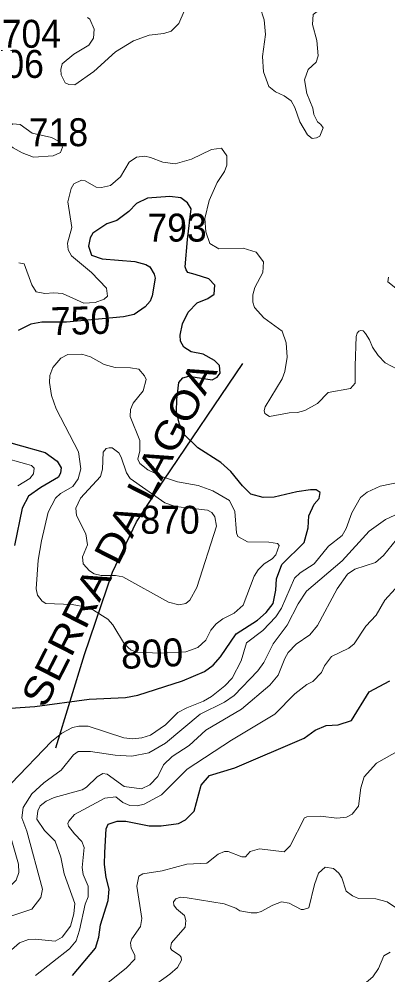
# Model space of a CAD drawing. Extents: x 499.9 to 555.3, y 9281.5 to 9336.8.
# Drawn here: x 540.62 to 542.72, y 9284.25 to 9289.72 of the extents above; entities that cross this region are included whole.
import ezdxf
from ezdxf.enums import TextEntityAlignment as Align

# ---------------------------------------------------------------- set-up
doc = ezdxf.new("R2010")
doc.units = 0
doc.header["$LTSCALE"] = 0.064
for name, color, linetype, lineweight in [('1', 7, 'Continuous', 25), ('2', 7, 'Continuous', 13), ('26', 7, 'Continuous', 25)]:
    doc.layers.add(name, color=color, linetype=linetype, lineweight=lineweight)
doc.layers.add('21', color=7, linetype='Continuous')
doc.layers.add('61', color=7, linetype='Continuous')

msp = doc.modelspace()

# ---------------------------------------------------------------- linework, layer by layer
at = {"layer": '1'}
for points in [[(541.6227, 9288.262), (541.5806, 9288.2744), (541.5701, 9288.289), (541.5654, 9288.3054), (541.578, 9288.4627), (541.5992, 9288.638), (541.5787, 9288.6731), (541.5405, 9288.7), (541.4766, 9288.7081), (541.3506, 9288.6982), (541.2871, 9288.6677), (541.243, 9288.6223), (541.1753, 9288.5719), (541.1182, 9288.5517), (541.0363, 9288.498), (541.0226, 9288.4717), (541.0126, 9288.4249), (541.0293, 9288.3723), (541.0913, 9288.3512), (541.2781, 9288.3373), (541.3409, 9288.3184), (541.3638, 9288.3053), (541.3875, 9288.2649), (541.394, 9288.2419), (541.3769, 9288.1409), (541.366, 9288.1101), (541.3368, 9288.0765), (541.274, 9288.0324), (541.212, 9288.0192), (541.0095, 9288), (540.8874, 9287.9885), (540.7455, 9287.99), (540.6821, 9287.9773), (540.6097, 9287.9425)], [(541.7302, 9288.1499), (541.7343, 9288.2004), (541.7014, 9288.2371), (541.6227, 9288.262)], [(540.5659, 9285.7798), (540.7065, 9285.7902), (541.0157, 9285.8315), (541.2248, 9285.8404), (541.295, 9285.8542), (541.5506, 9285.9365), (541.6759, 9285.9899), (541.7262, 9286.026), (541.7677, 9286.0735), (541.8575, 9286.206), (541.9797, 9286.2834), (542.0293, 9286.3273), (542.0676, 9286.379), (542.0834, 9286.4562), (542.0884, 9286.5198), (542.1178, 9286.6028), (542.2455, 9286.7285), (542.2679, 9286.8127), (542.2717, 9286.8803), (542.302, 9286.947), (542.3311, 9286.9792), (542.3375, 9287.0139), (542.3139, 9287.0289), (542.2817, 9287.0288), (542.2035, 9287.0177), (542.0738, 9286.9878), (542.0113, 9286.9862), (541.941, 9287.0051), (541.8935, 9287.0521), (541.8255, 9287.1342), (541.7698, 9287.1866), (541.6371, 9287.2701), (541.5552, 9287.3508), (541.5312, 9287.4111), (541.5153, 9287.4788), (541.517, 9287.5469), (541.5298, 9287.6448), (541.5524, 9287.6711), (541.5869, 9287.6797), (541.7204, 9287.6598), (541.748, 9287.6737), (541.7649, 9287.6979), (541.7616, 9287.7404), (541.7331, 9287.7707), (541.6688, 9287.8059), (541.5999, 9287.8204), (541.5569, 9287.8459), (541.5392, 9287.8798), (541.5361, 9287.914), (541.5501, 9287.9801), (541.5833, 9288.0469), (541.6331, 9288.1), (541.6942, 9288.1254), (541.7302, 9288.1499)], [(540.4919, 9287.3189), (540.7655, 9287.2438), (540.8332, 9287.1935), (540.856, 9287.1548), (540.853, 9287.1279), (540.8412, 9287.102), (540.7394, 9287.0429), (540.6691, 9286.9937), (540.633, 9286.9252), (540.5889, 9286.7108)], [(540.9216, 9284.2502), (541.0523, 9284.4071), (541.0711, 9284.47), (541.081, 9284.5407), (541.1254, 9284.6789), (541.1314, 9284.7436), (541.1126, 9284.8105), (541.1047, 9284.8849), (541.1065, 9284.9548), (541.1141, 9285.09), (541.1257, 9285.1157), (541.1765, 9285.1335), (541.2251, 9285.1328), (541.3585, 9285.1066), (541.4277, 9285.1066), (541.5264, 9285.1201), (541.5667, 9285.1406), (541.6169, 9285.191), (541.6571, 9285.3388), (541.7047, 9285.3943), (541.8486, 9285.4395), (542.2465, 9285.6092), (542.3088, 9285.6551), (542.3712, 9285.6818), (542.4407, 9285.6845), (542.517, 9285.7097), (542.6178, 9285.873), (542.7356, 9285.936)]]:
    msp.add_lwpolyline(points, dxfattribs=at)
at = {"layer": '2'}
for points in [[(541.9666, 9289.8735), (542.0165, 9289.7189), (542.0245, 9289.6354), (542.0072, 9289.5096), (542.0127, 9289.4227), (542.0434, 9289.3377), (542.0819, 9289.3068), (542.1318, 9289.2838), (542.1707, 9289.2556), (542.1919, 9289.2184), (542.2207, 9289.1357), (542.2645, 9289.0607), (542.2922, 9289.0413), (542.3157, 9289.0443), (542.3355, 9289.0537), (542.3549, 9289.1019), (542.3416, 9289.1213), (542.321, 9289.1359)], [(542.2679, 9289.4348), (542.3151, 9289.4781), (542.3253, 9289.5128), (542.3189, 9289.6011), (542.2931, 9289.6931), (542.2968, 9289.7499), (542.3944, 9289.8232), (542.4483, 9289.902), (542.4756, 9289.9209), (542.5321, 9289.9128), (542.5753, 9289.8797), (542.6539, 9289.843), (542.8073, 9289.8288)], [(541.0067, 9289.7334), (541.0197, 9289.7224), (541.0454, 9289.6663), (541.042, 9289.6149), (541.0136, 9289.5742), (540.928, 9289.5231), (540.8627, 9289.4682), (540.8537, 9289.4351), (540.8564, 9289.4044), (540.8793, 9289.3596), (540.9009, 9289.3498), (540.9334, 9289.3466), (541.0431, 9289.424), (541.1668, 9289.5363), (541.2704, 9289.6), (541.3601, 9289.6311), (541.4436, 9289.641), (541.4855, 9289.6543), (541.5282, 9289.6989), (541.5965, 9289.8557)], [(542.321, 9289.1359), (542.3014, 9289.1786), (542.2947, 9289.2134), (542.2612, 9289.2973), (542.2476, 9289.3765), (542.2679, 9289.4348)], [(541.8967, 9288.4132), (541.7585, 9288.4093), (541.7069, 9288.4391), (541.6826, 9288.5065), (541.6779, 9288.5823), (541.7017, 9288.685), (541.7484, 9288.7879), (541.7904, 9288.8515), (541.8031, 9288.8882), (541.8032, 9288.9415), (541.7725, 9288.9846), (541.7163, 9288.9772), (541.602, 9288.9213), (541.5072, 9288.8946), (541.438, 9288.9054), (541.3679, 9288.9323), (541.3352, 9288.9385), (541.2872, 9288.9344), (541.2448, 9288.9054), (541.1957, 9288.8219), (541.138, 9288.772), (541.0871, 9288.7593), (541.0569, 9288.7622), (540.9938, 9288.7985), (540.9719, 9288.8017), (540.9287, 9288.78), (540.9134, 9288.7536), (540.8947, 9288.6783), (540.9168, 9288.5314), (540.8933, 9288.4409), (540.8965, 9288.4038), (540.9157, 9288.369), (541.0287, 9288.2732), (541.1151, 9288.1836), (541.1202, 9288.1377), (541.1021, 9288.1213), (541.0498, 9288.1024), (540.9861, 9288.0979), (540.8634, 9288.1527), (540.8141, 9288.1574), (540.7624, 9288.1529), (540.7135, 9288.1636), (540.6877, 9288.2038), (540.6447, 9288.3222), (540.6136, 9288.3292)], [(542.7816, 9287.7189), (542.7095, 9287.7561), (542.6679, 9287.7979), (542.6361, 9287.8466), (542.6196, 9287.8885), (542.5967, 9287.9252), (542.5823, 9287.9393), (542.5692, 9287.9419), (542.5587, 9287.9378), (542.5496, 9287.927), (542.5436, 9287.9067), (542.537, 9287.7398), (542.5379, 9287.6397), (542.5098, 9287.6099), (542.3828, 9287.5875), (542.3214, 9287.5238), (542.2496, 9287.483), (542.2083, 9287.4719), (542.1603, 9287.4708), (542.0481, 9287.4496), (542.0208, 9287.4662), (542.0168, 9287.4836), (542.0235, 9287.5041), (542.1206, 9287.6641), (542.1359, 9287.7071), (542.1485, 9287.7892), (542.1423, 9287.8719), (542.1205, 9287.9374), (542.016, 9288.0149), (541.9623, 9288.0724), (541.9531, 9288.1043), (541.9515, 9288.1464), (541.9645, 9288.1885), (542.0099, 9288.2738), (542.0132, 9288.3351), (541.9719, 9288.3897), (541.8967, 9288.4132)], [(542.7279, 9288.2475), (542.7237, 9288.2198), (542.7891, 9288.169)], [(540.5094, 9287.2181), (540.6598, 9287.1773), (540.687, 9287.1691), (540.7014, 9287.1543), (540.6985, 9287.1216), (540.6773, 9287.094), (540.6087, 9287.0518)], [(541.2136, 9285.6112), (541.2645, 9285.6048), (541.3182, 9285.61), (541.3672, 9285.6254), (541.4531, 9285.6843), (541.524, 9285.7547), (541.5743, 9285.7821), (541.6696, 9285.8196), (541.7157, 9285.8462), (541.7922, 9285.9076), (541.8339, 9285.9523), (541.8857, 9286.0512), (541.9166, 9286.1536), (542.0102, 9286.2239), (542.0839, 9286.3024), (542.1155, 9286.3519), (542.1913, 9286.5243), (542.2219, 9286.5547), (542.303, 9286.6058), (542.3846, 9286.7077), (542.4636, 9286.7683), (542.4866, 9286.8093), (542.5179, 9286.8987), (542.5679, 9286.9851), (542.6061, 9287.0167), (542.6803, 9287.0498), (542.9294, 9287.1022)], [(542.7649, 9286.8855), (542.7106, 9286.8604), (542.6167, 9286.7935), (542.4631, 9286.6243), (542.2589, 9286.4499), (542.2108, 9286.3766), (542.1486, 9286.2557), (542.0675, 9286.1489), (542.016, 9286.0417), (541.9802, 9285.9932), (541.8462, 9285.853), (541.7896, 9285.8152), (541.6506, 9285.7463), (541.4528, 9285.5798), (541.3568, 9285.525), (541.2603, 9285.5061), (541.1659, 9285.5108), (541.0234, 9285.533), (540.9535, 9285.5327), (540.9276, 9285.5133), (540.8556, 9285.4259), (540.7562, 9285.352), (540.6888, 9285.2906), (540.6384, 9285.2114), (540.6304, 9285.1518), (540.6591, 9285.0772), (540.7493, 9284.7444), (540.7402, 9284.6968), (540.689, 9284.6308), (540.5684, 9284.5905)], [(542.7731, 9286.7447), (542.6988, 9286.653), (542.6528, 9286.6131), (542.5361, 9286.5758), (542.4929, 9286.547)], [(542.4929, 9286.547), (542.4336, 9286.4641), (542.3211, 9286.2526), (542.2775, 9286.2), (542.2006, 9286.1467), (542.1545, 9286.0992)], [(540.7097, 9284.2512), (540.9045, 9284.402), (540.9418, 9284.4483), (540.9615, 9284.509), (540.9938, 9284.6581), (541.0109, 9284.6999), (541.0104, 9284.7625), (540.9824, 9284.8289), (540.9757, 9284.8678), (540.9881, 9284.9831), (540.9751, 9285.0163), (540.9316, 9285.0618), (540.8976, 9285.1051), (540.895, 9285.1202), (540.8999, 9285.1341), (540.9329, 9285.1716), (541.1063, 9285.2661), (541.1696, 9285.2734), (541.2097, 9285.2404), (541.2494, 9285.2225), (541.2901, 9285.2212), (541.3307, 9285.2314), (541.4298, 9285.2834), (541.5773, 9285.4307), (541.8297, 9285.5979), (542.0772, 9285.7454), (542.1927, 9285.862), (542.2618, 9285.9156), (542.2948, 9285.9337), (542.3439, 9285.9845), (542.3624, 9286.0223), (542.4014, 9286.0753), (542.502, 9286.1241), (542.5321, 9286.1475), (542.5987, 9286.2501), (542.6574, 9286.3124), (542.7069, 9286.3983), (542.7664, 9286.4628)], [(542.1545, 9286.0992), (542.1344, 9286.0646), (542.0964, 9285.9698), (542.0494, 9285.9113), (541.8876, 9285.775), (541.6827, 9285.6548), (541.5879, 9285.5674), (541.4914, 9285.5028), (541.4417, 9285.456), (541.408, 9285.3893), (541.363, 9285.341), (541.3154, 9285.3179), (541.2157, 9285.3314), (541.1196, 9285.4021), (541.0945, 9285.4054), (541.0623, 9285.387), (541.0017, 9285.3278), (540.9771, 9285.3126), (540.8167, 9285.2699), (540.7698, 9285.2484), (540.7359, 9285.2215), (540.7226, 9285.1932), (540.7167, 9285.1441), (540.7614, 9285.0807), (540.8227, 9285.0189), (540.8549, 9284.9276), (540.8739, 9284.8328), (540.9341, 9284.663), (540.9282, 9284.6025), (540.9086, 9284.532), (540.8626, 9284.4701), (540.8221, 9284.4462), (540.7066, 9284.4586), (540.6702, 9284.4555), (540.617, 9284.4375), (540.5713, 9284.3975)], [(540.8007, 9285.5887), (540.8596, 9285.6374), (540.9201, 9285.6698), (540.9575, 9285.6779), (541.0115, 9285.6776), (541.2136, 9285.6112)], [(539.4244, 9284.1395), (539.5556, 9284.2752), (539.7038, 9284.3291), (539.7533, 9284.3554), (539.7973, 9284.3883), (539.8761, 9284.4716), (539.9056, 9284.4948), (540.0845, 9284.5504), (540.1934, 9284.596), (540.2865, 9284.6502), (540.41, 9284.7447), (540.4473, 9284.7599), (540.5528, 9284.7508), (540.5991, 9284.7967), (540.6142, 9284.8396), (540.6126, 9284.8877), (540.5339, 9285.1604), (540.5254, 9285.229), (540.5413, 9285.2975), (540.5712, 9285.3499), (540.8007, 9285.5887)], [(541.104, 9284.194), (541.2303, 9284.2933), (541.277, 9284.343), (541.2778, 9284.3664), (541.2571, 9284.4071), (541.2529, 9284.4381), (541.2595, 9284.4608), (541.3097, 9284.5305), (541.3175, 9284.5763), (541.2879, 9284.7609), (541.3011, 9284.8197), (541.3241, 9284.8314), (541.4339, 9284.8496), (541.5741, 9284.8869), (541.6887, 9284.8935), (541.754, 9284.944), (541.7905, 9284.9599), (541.8103, 9284.9597), (541.8891, 9284.9298), (541.9097, 9284.9303), (541.9372, 9284.9599), (541.9912, 9284.9758), (542.131, 9284.9574), (542.1664, 9284.992), (542.2476, 9285.1522), (542.2617, 9285.159), (542.3388, 9285.1621), (542.4321, 9285.1513), (542.4879, 9285.1573), (542.5196, 9285.1741), (542.556, 9285.2187), (542.5691, 9285.3238), (542.5881, 9285.3874), (542.6591, 9285.4657), (542.79, 9285.5395)], [(542.7686, 9284.6401), (542.7198, 9284.6712), (542.6563, 9284.6894), (542.5564, 9284.6913), (542.5227, 9284.706), (542.4851, 9284.7338), (542.4608, 9284.8098), (542.4435, 9284.8369), (542.4134, 9284.8618), (542.3658, 9284.8703), (542.328, 9284.8361), (542.3051, 9284.7707), (542.2717, 9284.6384), (542.2426, 9284.6276), (542.2283, 9284.6288), (542.1597, 9284.6639), (542.1158, 9284.672), (542.0667, 9284.6534), (542.0007, 9284.6159), (541.9745, 9284.6084), (541.9426, 9284.6084), (541.8784, 9284.6209), (541.8542, 9284.6361), (541.7873, 9284.6608), (541.5773, 9284.6943), (541.5393, 9284.6984), (541.5112, 9284.6895), (541.4982, 9284.6716), (541.5007, 9284.6528), (541.5158, 9284.6318), (541.561, 9284.5938), (541.569, 9284.5644), (541.5645, 9284.5269), (541.4877, 9284.4367), (541.4818, 9284.4074), (541.489, 9284.3954), (541.533, 9284.3675), (541.5416, 9284.3558), (541.5436, 9284.3379), (541.5205, 9284.2956), (541.4777, 9284.2589), (541.3607, 9284.1746)], [(541.458, 9283.7571), (541.5417, 9283.8675), (541.6027, 9283.9145), (541.6733, 9283.9915), (541.7401, 9284.0831), (541.7695, 9284.1349), (541.7938, 9284.1738), (541.8084, 9284.1872), (541.8241, 9284.1854), (541.835, 9284.1745), (541.8494, 9284.1253), (541.883, 9283.8716), (541.9024, 9283.8267), (541.9617, 9283.7909), (541.9848, 9283.7904), (542.0602, 9283.829), (542.2188, 9283.9504), (542.3046, 9284.0061), (542.4392, 9284.0749), (542.6382, 9284.2418), (542.6705, 9284.2901), (542.7009, 9284.3625), (542.7382, 9284.3841)]]:
    msp.add_lwpolyline(points, dxfattribs=at)
for points in [[(540.5819, 9288.9879), (540.6341, 9288.9578), (540.6976, 9288.9336), (540.8099, 9288.9412), (540.8517, 9288.9609), (540.8635, 9288.9899), (540.8488, 9289.0205), (540.8016, 9289.0459), (540.6905, 9289.0718), (540.6213, 9289.1199), (540.5797, 9289.1249), (540.554, 9289.106), (540.5389, 9289.0851), (540.53, 9289.0452), (540.5556, 9289.0079)], [(541.2187, 9286.1465), (541.2563, 9286.1115), (541.2882, 9286.1008), (541.4227, 9286.0955), (541.5691, 9286.1035), (541.6369, 9286.1275), (541.6839, 9286.1688), (541.7116, 9286.2267), (541.7419, 9286.2624), (541.7809, 9286.2914), (541.846, 9286.3235), (541.896, 9286.3689), (541.9597, 9286.5363), (541.9827, 9286.5717), (542.0171, 9286.6063), (542.062, 9286.6341), (542.0829, 9286.6578), (542.1021, 9286.7107), (542.0927, 9286.7232), (542.0439, 9286.7297), (541.9211, 9286.7317), (541.8658, 9286.7618), (541.859, 9286.7841), (541.8497, 9286.9064), (541.8185, 9286.9689), (541.723, 9287.0246), (541.6394, 9287.054), (541.5208, 9287.0751), (541.4356, 9287.1046), (541.3514, 9287.1438), (541.3065, 9287.181), (541.2955, 9287.2047), (541.3051, 9287.2527), (541.3064, 9287.313), (541.2512, 9287.4501), (541.2527, 9287.4899), (541.2687, 9287.5259), (541.3252, 9287.5968), (541.3415, 9287.6609), (541.3336, 9287.6817), (541.3, 9287.7201), (541.2526, 9287.7278), (541.1641, 9287.7303), (541.1015, 9287.7464), (541.0234, 9287.7914), (540.9744, 9287.8053), (540.8937, 9287.8042), (540.854, 9287.783), (540.8083, 9287.7298), (540.7912, 9287.6848), (540.7898, 9287.6435), (540.8006, 9287.5702), (540.8277, 9287.4939), (540.9546, 9287.2463), (540.9677, 9287.1508), (540.9531, 9287.093), (540.9225, 9287.0483), (540.8527, 9287.0087), (540.8241, 9286.9825), (540.7826, 9286.9014), (540.7432, 9286.7388), (540.7239, 9286.6267), (540.7134, 9286.464), (540.7216, 9286.427), (540.7477, 9286.3932), (540.769, 9286.3784), (540.9192, 9286.3733), (541.0004, 9286.3577), (541.0418, 9286.3418), (541.1226, 9286.29), (541.1523, 9286.2572)], [(541.7442, 9286.821), (541.734, 9286.8758), (541.7183, 9286.9007), (541.6933, 9286.9141), (541.5105, 9286.9353), (541.4499, 9286.956), (541.25, 9287.0955), (541.2304, 9287.1279), (541.1999, 9287.2169), (541.1856, 9287.2422), (541.1487, 9287.2694), (541.1316, 9287.2703), (541.1127, 9287.2659), (541.096, 9287.2453), (541.0918, 9287.1477), (541.0805, 9287.1056), (540.9663, 9286.9813), (540.9393, 9286.9256), (540.944, 9286.8828), (540.9981, 9286.7777), (541.0071, 9286.7149), (540.9791, 9286.6471), (540.9827, 9286.6056), (541.0181, 9286.5666), (541.0458, 9286.5486), (541.0847, 9286.539), (541.1666, 9286.5404), (541.2086, 9286.5321), (541.4706, 9286.387), (541.5284, 9286.3707), (541.5688, 9286.3789), (541.5915, 9286.399), (541.631, 9286.4715)]]:
    msp.add_lwpolyline(points, close=True, dxfattribs=at)
at = {"layer": '26'}
msp.add_lwpolyline([(540.8256, 9285.5533), (540.9895, 9286.0881), (541.149, 9286.5582), (541.287, 9286.8472), (541.4423, 9287.0844), (541.8951, 9287.7528)], dxfattribs=at)

# ---------------------------------------------------------------- texts
at = {"layer": '21', "width": 0.95}
for s, p in [('704', (540.5161, 9289.5595)), ('706', (540.4184, 9289.3871)), ('718', (540.6712, 9288.9963)), ('793', (541.3493, 9288.4504)), ('870', (541.3091, 9286.7783))]:
    msp.add_text(s, height=0.16, dxfattribs=at).set_placement(p)
at = {"layer": '26', "width": 1.15}
msp.add_text('SERRA DA LAGOA', height=0.16, rotation=62.942, dxfattribs=at).set_placement((541.2582, 9286.7414), align=Align.CENTER)
at = {"layer": '61', "width": 0.95}
msp.add_text('750', height=0.16, rotation=1.592, dxfattribs=at).set_placement((540.9696, 9287.9189), align=Align.CENTER)
at = {"layer": '61'}
msp.add_text('800', height=0.16, rotation=3.013, dxfattribs=at).set_placement((541.3799, 9286.0132), align=Align.CENTER)

doc.saveas('drawing.dxf')
